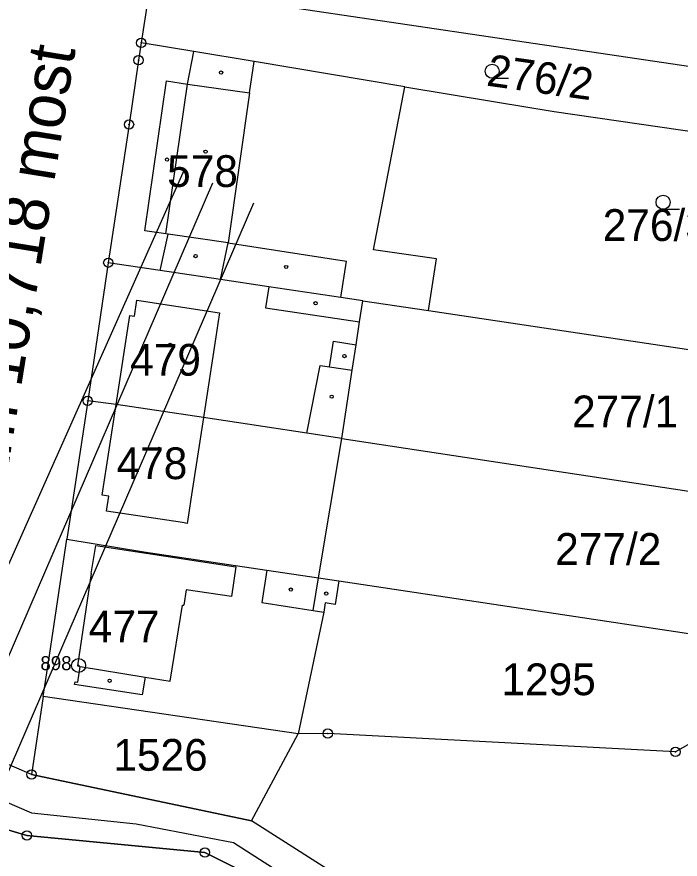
# Model space of a CAD drawing. Extents: x -537341 to -532984, y -1143469 to -1141314.
# Drawn here: x -534383 to -534311.9, y -1143026 to -1142935.8 of the extents above; entities that cross this region are included whole.
import ezdxf

# ---------------------------------------------------------------- set-up
doc = ezdxf.new("R2010")
doc.units = 0
for name, color, linetype in [('Hranice parcel', 7, 'Continuous'), ('parcelní_č_2000', 7, 'Continuous'), ('u_obec_Horní_Moš', 7, 'Continuous'), ('u_objekty', 7, 'Continuous'), ('u_osa_toku', 7, 'Continuous'), ('u_pricne', 7, 'Continuous'), ('Vnitřní kresba', 7, 'Continuous'), ('Značky bodu BP', 7, 'Continuous'), ('Značky budov', 7, 'Continuous'), ('Značky kultur', 7, 'Continuous')]:
    doc.layers.add(name, color=color, linetype=linetype)

msp = doc.modelspace()

# ---------------------------------------------------------------- linework, layer by layer
at = {"layer": 'Hranice parcel'}
for p, q in [((-534368.79, -1142932.48), (-534369.7, -1142938.55)), ((-534368.79, -1142932.48), (-534285.82, -1142944.76)), ((-534373.23, -1142962.09), (-534375.44, -1142976.89)), ((-534345.95, -1142966.17), (-534338.9, -1142967.22)), ((-534338.9, -1142967.22), (-534290.15, -1142974.52)), ((-534375.44, -1142976.89), (-534377.66, -1142991.7)), ((-534350.7, -1142995.85), (-534348.2, -1142980.92)), ((-534348.2, -1142980.92), (-534292.32, -1142989.39)), ((-534350.7, -1142995.85), (-534348.53, -1142996.17)), ((-534348.53, -1142996.17), (-534294.49, -1143004.27)), ((-534380.2, -1143008.54), (-534381.46, -1143016.89)), ((-534352.88, -1143012.56), (-534380.2, -1143008.54)), ((-534381.46, -1143016.89), (-534396.63, -1143010.5)), ((-534357.88, -1143021.87), (-534352.88, -1143012.56)), ((-534381.46, -1143016.89), (-534357.88, -1143021.87))]:
    msp.add_line(p, q, dxfattribs=at)
for points in [[(-534369.7, -1142938.55), (-534369.98, -1142940.41), (-534371.01, -1142947.29), (-534373.23, -1142962.09)], [(-534341.45, -1142943.24), (-534357.61, -1142940.55), (-534364.08, -1142939.48), (-534369.7, -1142938.55)], [(-534338.9, -1142967.22), (-534338.07, -1142961.68), (-534344.8, -1142960.7), (-534341.45, -1142943.24)], [(-534341.45, -1142943.24), (-534331.74, -1142944.85), (-534325.43, -1142945.89), (-534286.8, -1142951.49)], [(-534345.95, -1142966.17), (-534348.31, -1142965.82), (-534356.04, -1142964.66), (-534361.19, -1142963.89), (-534367.66, -1142962.92), (-534373.23, -1142962.09)], [(-534348.2, -1142980.92), (-534347.09, -1142973.61), (-534346.67, -1142970.88), (-534346.3, -1142968.44), (-534345.95, -1142966.17)], [(-534348.2, -1142980.92), (-534351.96, -1142980.35), (-534363.03, -1142978.67), (-534372.4, -1142977.29), (-534375.44, -1142976.89)], [(-534380.2, -1143008.54), (-534379.64, -1143004.87), (-534377.66, -1142991.7)], [(-534377.66, -1142991.7), (-534369.42, -1142993.04), (-534356.24, -1142995.02), (-534350.7, -1142995.85)], [(-534348.53, -1142996.17), (-534348.91, -1142998.69), (-534349.99, -1142998.52), (-534350.14, -1142999.52), (-534352.88, -1143012.56)], [(-534294.49, -1143004.27), (-534312.44, -1143014.49), (-534349.71, -1143012.52), (-534352.88, -1143012.56)], [(-534282.11, -1143079.68), (-534309.94, -1143068.18), (-534325.51, -1143056.45), (-534346.72, -1143035.39), (-534357.53, -1143027.93), (-534362.88, -1143025.27), (-534381.95, -1143023.43), (-534397.75, -1143018.75)], [(-534254.16, -1143083.21), (-534306.64, -1143062.38), (-534343.69, -1143030.88), (-534357.88, -1143021.87)]]:
    msp.add_lwpolyline(points, dxfattribs=at)
at = {"layer": 'u_obec_Horní_Moš'}
for p, q in [((-534381.46, -1143016.89), (-534396.63, -1143010.5)), ((-534357.88, -1143021.87), (-534381.46, -1143016.89))]:
    msp.add_line(p, q, dxfattribs=at)
for points in [[(-534397.75, -1143018.75), (-534381.95, -1143023.43), (-534362.88, -1143025.27), (-534357.53, -1143027.93), (-534346.72, -1143035.39), (-534325.51, -1143056.45), (-534309.94, -1143068.18), (-534282.11, -1143079.68)], [(-534362.88, -1143025.27), (-534381.95, -1143023.43), (-534397.75, -1143018.75)], [(-534254.16, -1143083.21), (-534306.64, -1143062.38), (-534343.69, -1143030.88), (-534357.88, -1143021.87)], [(-534346.72, -1143035.39), (-534357.53, -1143027.93), (-534362.88, -1143025.27)]]:
    msp.add_lwpolyline(points, dxfattribs=at)
at = {"layer": 'u_osa_toku'}
msp.add_lwpolyline([(-534484.457, -1142953.581), (-534476.389, -1142957.2), (-534453.494, -1142977.653), (-534439.757, -1142986.114), (-534420.7, -1142998.761), (-534398.328, -1143013.021), (-534394.258, -1143015.615), (-534393.061, -1143016.024), (-534381.48, -1143021.024), (-534370.243, -1143022.179), (-534359.806, -1143024.191), (-534342.705, -1143035.16), (-534323.172, -1143054.062), (-534315.774, -1143059.466), (-534304.566, -1143066.225), (-534255.2, -1143086.242), (-534194.495, -1143118.949)], dxfattribs=at)
at = {"layer": 'u_pricne'}
for p, q in [((-534365.09, -1142952.129), (-534422.227, -1143080.248)), ((-534362.074, -1142953.585), (-534417.838, -1143082.745)), ((-534357.683, -1142955.706), (-534413.578, -1143085.169))]:
    msp.add_line(p, q, dxfattribs=at)
at = {"layer": 'Vnitřní kresba'}
for p, q in [((-534364.74, -1142942.96), (-534364.08, -1142939.48)), ((-534358.09, -1142943.91), (-534357.61, -1142940.55)), ((-534369.33, -1142958.67), (-534367.01, -1142942.63)), ((-534367.05, -1142959), (-534364.74, -1142942.96)), ((-534367.01, -1142942.63), (-534364.74, -1142942.96)), ((-534364.74, -1142942.96), (-534358.09, -1142943.91)), ((-534358.09, -1142943.91), (-534360.39, -1142959.96)), ((-534367.05, -1142959), (-534369.33, -1142958.67)), ((-534367.66, -1142962.92), (-534366.8, -1142959.04)), ((-534366.8, -1142959.04), (-534367.05, -1142959)), ((-534360.39, -1142959.96), (-534366.8, -1142959.04)), ((-534361.19, -1142963.89), (-534360.39, -1142959.96)), ((-534360.39, -1142959.96), (-534347.7, -1142961.93)), ((-534348.31, -1142965.82), (-534347.7, -1142961.93)), ((-534356.04, -1142964.66), (-534356.38, -1142966.94)), ((-534370.43, -1142967.81), (-534370.17, -1142966.12)), ((-534370.17, -1142966.12), (-534361.32, -1142967.47)), ((-534361.32, -1142967.47), (-534361.5, -1142968.61)), ((-534356.38, -1142966.94), (-534346.3, -1142968.44)), ((-534372.4, -1142977.29), (-534370.94, -1142967.73)), ((-534370.94, -1142967.73), (-534370.43, -1142967.81)), ((-534361.5, -1142968.61), (-534361.71, -1142970.03)), ((-534361.71, -1142970.03), (-534363.03, -1142978.67)), ((-534349.52, -1142973.24), (-534349.1, -1142970.51)), ((-534349.1, -1142970.51), (-534346.67, -1142970.88)), ((-534351.96, -1142980.35), (-534350.53, -1142973.09)), ((-534350.53, -1142973.09), (-534349.52, -1142973.24)), ((-534349.52, -1142973.24), (-534347.09, -1142973.61)), ((-534373.88, -1142986.99), (-534372.4, -1142977.29)), ((-534363.03, -1142978.67), (-534364.37, -1142987.41)), ((-534373.19, -1142987.09), (-534373.88, -1142986.99)), ((-534373.43, -1142988.69), (-534373.19, -1142987.09)), ((-534364.37, -1142987.41), (-534364.55, -1142988.64)), ((-534365.26, -1142989.93), (-534373.43, -1142988.69)), ((-534364.55, -1142988.64), (-534364.76, -1142990.01)), ((-534364.76, -1142990.01), (-534365.26, -1142989.93)), ((-534375.06, -1142995.37), (-534374.57, -1142992.38)), ((-534374.57, -1142992.38), (-534359.56, -1142994.65)), ((-534375.06, -1142995.37), (-534376.55, -1143005.28)), ((-534359.56, -1142994.65), (-534360.03, -1142997.83)), ((-534356.24, -1142995.02), (-534356.76, -1142998.5)), ((-534351.27, -1142999.34), (-534350.7, -1142995.85)), ((-534364.88, -1142997.12), (-534365.12, -1142998.78)), ((-534360.03, -1142997.83), (-534364.88, -1142997.12)), ((-534366.6, -1143006.91), (-534365.26, -1142998.76)), ((-534365.26, -1142998.76), (-534365.12, -1142998.78)), ((-534356.76, -1142998.5), (-534351.27, -1142999.34)), ((-534351.27, -1142999.34), (-534350.14, -1142999.52)), ((-534376.55, -1143005.28), (-534376.25, -1143005.32)), ((-534376.49, -1143007.01), (-534376.25, -1143005.32)), ((-534376.25, -1143005.32), (-534369.29, -1143006.47)), ((-534376.84, -1143007.26), (-534376.8, -1143006.97)), ((-534376.8, -1143006.97), (-534376.49, -1143007.01)), ((-534369.29, -1143006.47), (-534369.6, -1143008.38)), ((-534369.29, -1143006.47), (-534366.6, -1143006.91)), ((-534369.6, -1143008.38), (-534376.84, -1143007.26))]:
    msp.add_line(p, q, dxfattribs=at)
at = {"layer": 'Značky bodu BP'}
for centre, radius in [((-534369.7, -1142938.55), 0.5), ((-534369.7, -1142938.55), 0.0303), ((-534369.98, -1142940.41), 0.5), ((-534369.98, -1142940.41), 0.0303), ((-534371.01, -1142947.29), 0.5), ((-534371.01, -1142947.29), 0.0303), ((-534373.23, -1142962.09), 0.5), ((-534373.23, -1142962.09), 0.0303), ((-534375.44, -1142976.89), 0.5), ((-534375.44, -1142976.89), 0.0303), ((-534376.41, -1143005.23), 0.75), ((-534376.41, -1143005.23), 0.03), ((-534349.71, -1143012.52), 0.5), ((-534349.71, -1143012.52), 0.0303), ((-534312.44, -1143014.49), 0.5), ((-534312.44, -1143014.49), 0.0303), ((-534381.46, -1143016.89), 0.5), ((-534381.46, -1143016.89), 0.0303), ((-534381.95, -1143023.43), 0.5), ((-534381.95, -1143023.43), 0.0303), ((-534362.88, -1143025.27), 0.5), ((-534362.88, -1143025.27), 0.0303)]:
    msp.add_circle(centre, radius, dxfattribs=at)
at = {"layer": 'Značky budov'}
for centre in [(-534361.147, -1142941.729), (-534362.807, -1142950.199), (-534366.937, -1142951.049), (-534363.877, -1142961.389), (-534354.167, -1142962.549), (-534351.017, -1142966.429), (-534366.597, -1142970.899), (-534347.917, -1142972.089), (-534349.287, -1142976.439), (-534367.787, -1142982.039), (-534353.667, -1142997.099), (-534349.877, -1142997.529), (-534370.707, -1142999.509), (-534373.087, -1143006.869)]:
    msp.add_circle(centre, 0.175, dxfattribs=at)
at = {"layer": 'Značky kultur'}
for p, q in [((-534332.083, -1142942.34), (-534330.333, -1142942.34)), ((-534313.763, -1142956.37), (-534312.013, -1142956.37))]:
    msp.add_line(p, q, dxfattribs=at)
for centre in [(-534332.083, -1142941.59), (-534313.763, -1142955.62)]:
    msp.add_circle(centre, 0.75, dxfattribs=at)

# ---------------------------------------------------------------- texts
at = {"layer": 'parcelní_č_2000'}
msp.add_text('276/2', height=3.4, rotation=352, dxfattribs=at).set_placement((-534332.79, -1142943.112))
for s, p in [('578', (-534366.925, -1142953.98)), ('276/3', (-534320.237, -1142959.76)), ('479', (-534370.888, -1142974.19)), ('277/1', (-534323.521, -1142979.72)), ('478', (-534372.348, -1142985.27)), ('277/2', (-534325.333, -1142994.45)), ('477', (-534375.328, -1143002.76)), ('1295', (-534331.093, -1143008.41)), ('1526', (-534372.693, -1143016.5))]:
    msp.add_text(s, height=3.4, dxfattribs=at).set_placement(p)
at = {"layer": 'u_objekty'}
msp.add_text('ø. km 10,718 most', height=5, rotation=80.84912, dxfattribs=at).set_placement((-534385.542, -1142993.884))
at = {"layer": 'Značky bodu BP'}
msp.add_text('898', height=1.5, dxfattribs=at).set_placement((-534380.513, -1143005.73))

doc.saveas('drawing.dxf')
